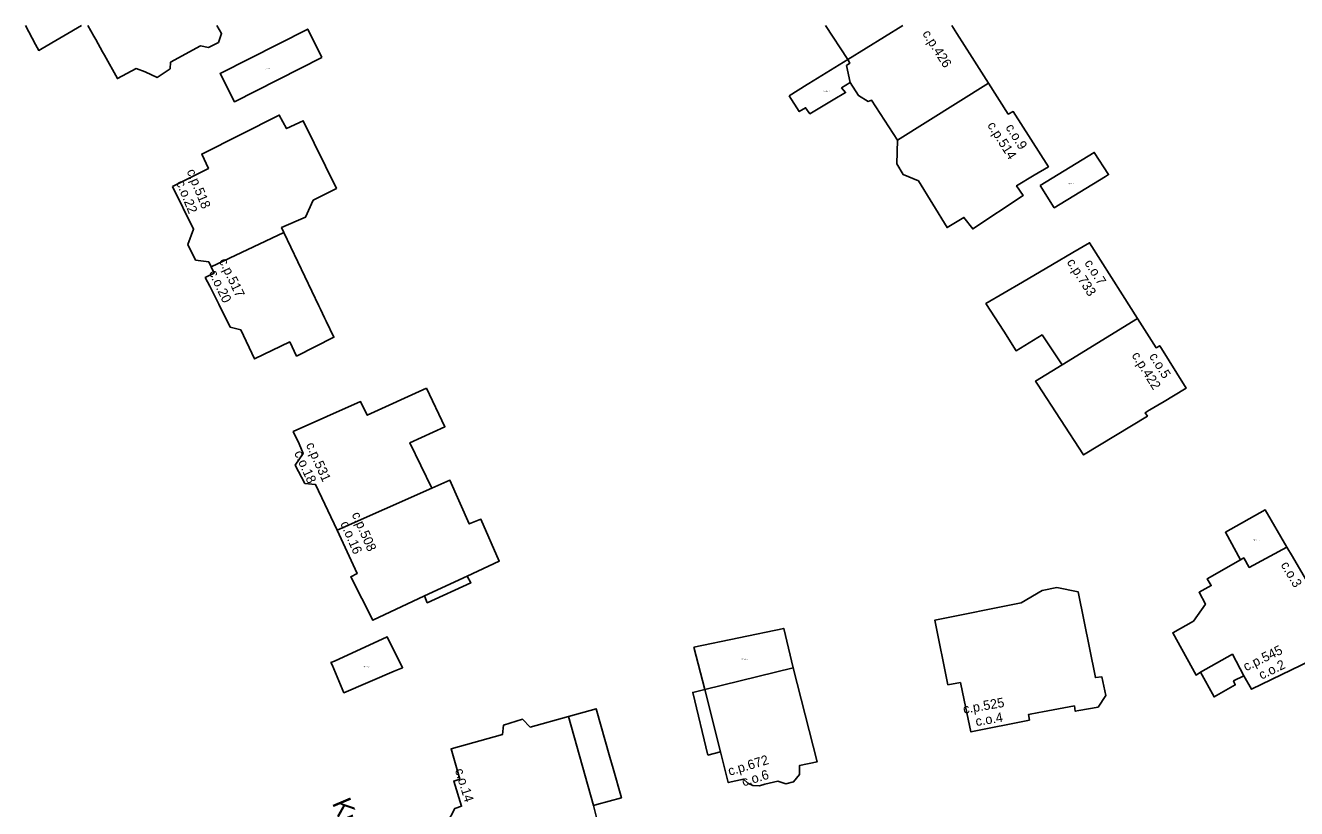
# Model space of a CAD drawing. Extents: x -600391 to -599491, y -1160176 to -1159402.
# Drawn here: x -600139.6 to -600005.8, y -1159484.2 to -1159401.8 of the extents above; entities that cross this region are included whole.
import ezdxf

# ---------------------------------------------------------------- set-up
doc = ezdxf.new("R2010")
doc.units = 0
for name, color, linetype in [('Level 10', 7, 'Continuous'), ('Level 11', 7, 'Continuous'), ('Level 12', 7, 'Continuous'), ('Level 24', 7, 'Continuous'), ('Level 25', 7, 'Continuous'), ('Level 61', 7, 'Continuous'), ('Level 62', 7, 'Continuous')]:
    doc.layers.add(name, color=color, linetype=linetype)

msp = doc.modelspace()

# ---------------------------------------------------------------- linework, layer by layer
at = {"layer": 'Level 61'}
for p, q in [((-600138.53, -1159403.77), (-600139.6, -1159401.77)), ((-600133.7, -1159401.77), (-600137.84, -1159404.2)), ((-600132.39, -1159402.91), (-600133.02, -1159401.77)), ((-600119.44, -1159401.77), (-600118.95, -1159402.63)), ((-600053.03, -1159405.36), (-600055.35, -1159401.77)), ((-600047.22, -1159401.77), (-600053.03, -1159405.36)), ((-600053.03, -1159405.36), (-600047.22, -1159401.77)), ((-600042.08, -1159401.77), (-600041.53, -1159402.63))]:
    msp.add_line(p, q, dxfattribs=at)
for points in [[(-600119.11, -1159406.82), (-600109.88, -1159402.16)], [(-600109.88, -1159402.16), (-600108.38, -1159405.14)], [(-600132.2, -1159403.26), (-600132.39, -1159402.91)], [(-600131.48, -1159404.56), (-600132.2, -1159403.26)], [(-600119.27, -1159403.55), (-600120.32, -1159404.11)], [(-600118.95, -1159402.63), (-600119.27, -1159403.55)], [(-600041.53, -1159402.63), (-600039.92, -1159405.16)], [(-600138.19, -1159404.4), (-600138.53, -1159403.77)], [(-600137.84, -1159404.2), (-600138.19, -1159404.4)], [(-600131.29, -1159404.91), (-600131.48, -1159404.56)], [(-600129.92, -1159407.37), (-600131.29, -1159404.91)], [(-600121.18, -1159403.92), (-600124.33, -1159405.65)], [(-600120.32, -1159404.11), (-600121.18, -1159403.92)], [(-600127.95, -1159406.31), (-600129.92, -1159407.37)], [(-600126.98, -1159406.66), (-600127.95, -1159406.31)], [(-600124.33, -1159405.65), (-600124.36, -1159406.33)], [(-600108.38, -1159405.14), (-600117.6, -1159409.81)], [(-600057.13, -1159407.89), (-600053.03, -1159405.36)], [(-600052.79, -1159405.74), (-600053.15, -1159406)], [(-600053.15, -1159406), (-600052.79, -1159405.74)], [(-600053.15, -1159406), (-600052.78, -1159407.77)], [(-600052.78, -1159407.77), (-600053.15, -1159406)], [(-600053.03, -1159405.36), (-600052.79, -1159405.74)], [(-600052.79, -1159405.74), (-600053.03, -1159405.36)], [(-600039.92, -1159405.16), (-600038.19, -1159407.86)], [(-600125.74, -1159407.25), (-600126.98, -1159406.66)], [(-600124.36, -1159406.33), (-600125.74, -1159407.25)], [(-600117.6, -1159409.81), (-600119.11, -1159406.82)], [(-600059.18, -1159409.18), (-600057.29, -1159407.99)], [(-600057.29, -1159407.99), (-600057.13, -1159407.89)], [(-600053.25, -1159408.83), (-600054.57, -1159409.61)], [(-600052.78, -1159407.77), (-600053.68, -1159408.35)], [(-600053.68, -1159408.35), (-600053.25, -1159408.83)], [(-600051.9, -1159409.15), (-600052.78, -1159407.77)], [(-600047.77, -1159413.85), (-600038.19, -1159407.86)], [(-600038.19, -1159407.86), (-600047.77, -1159413.85)], [(-600038.19, -1159407.86), (-600036.13, -1159411.1)], [(-600058.13, -1159410.84), (-600059.18, -1159409.18)], [(-600054.72, -1159409.7), (-600057.01, -1159411.06)], [(-600054.57, -1159409.61), (-600054.72, -1159409.7)], [(-600050.86, -1159409.76), (-600051.9, -1159409.15)], [(-600050.54, -1159409.62), (-600050.86, -1159409.76)], [(-600047.77, -1159413.85), (-600050.54, -1159409.62)], [(-600121.04, -1159415.31), (-600112.88, -1159411.21)], [(-600112.88, -1159411.21), (-600112.1, -1159412.63)], [(-600057.47, -1159410.43), (-600058.13, -1159410.84)], [(-600057.01, -1159411.06), (-600057.47, -1159410.43)], [(-600036.13, -1159411.1), (-600035.6, -1159410.83)], [(-600035.6, -1159410.83), (-600031.89, -1159416.64)], [(-600112.1, -1159412.63), (-600110.35, -1159411.81)], [(-600110.35, -1159411.81), (-600106.85, -1159418.93)], [(-600047.87, -1159416.35), (-600047.77, -1159413.85)], [(-600120.33, -1159416.82), (-600121.04, -1159415.31)], [(-600032.75, -1159418.63), (-600027.07, -1159415.13)], [(-600027.07, -1159415.13), (-600025.57, -1159417.47)], [(-600124.11, -1159418.71), (-600120.33, -1159416.82)], [(-600047.18, -1159417.47), (-600047.87, -1159416.35)], [(-600031.89, -1159416.64), (-600033.41, -1159417.53)], [(-600045.58, -1159418.12), (-600047.18, -1159417.47)], [(-600042.56, -1159423.05), (-600045.58, -1159418.12)], [(-600033.41, -1159417.53), (-600035.24, -1159418.64)], [(-600025.89, -1159417.66), (-600031.29, -1159420.96)], [(-600025.57, -1159417.47), (-600025.89, -1159417.66)], [(-600121.9, -1159423.23), (-600124.11, -1159418.71)], [(-600106.85, -1159418.93), (-600109.3, -1159420.17)], [(-600034.55, -1159419.67), (-600039.86, -1159423.19)], [(-600035.24, -1159418.64), (-600034.55, -1159419.67)], [(-600031.29, -1159420.96), (-600032.75, -1159418.63)], [(-600109.3, -1159420.17), (-600110.1, -1159421.94)], [(-600110.1, -1159421.94), (-600112.63, -1159423.05)], [(-600040.79, -1159421.98), (-600042.56, -1159423.05)], [(-600039.86, -1159423.19), (-600040.79, -1159421.98)], [(-600122.51, -1159424.82), (-600121.9, -1159423.23)], [(-600120.05, -1159427.18), (-600112.39, -1159423.56)], [(-600112.39, -1159423.56), (-600120.05, -1159427.18)], [(-600112.63, -1159423.05), (-600112.39, -1159423.56)], [(-600112.39, -1159423.56), (-600108.7, -1159431.29)], [(-600121.69, -1159426.47), (-600122.51, -1159424.82)], [(-600029.32, -1159425.67), (-600027.56, -1159424.64)], [(-600027.56, -1159424.64), (-600024.08, -1159430.14)], [(-600031.48, -1159426.94), (-600029.32, -1159425.67)], [(-600120.3, -1159426.67), (-600121.69, -1159426.47)], [(-600120.05, -1159427.18), (-600120.3, -1159426.67)], [(-600119.73, -1159427.84), (-600120.05, -1159427.18)], [(-600034.62, -1159428.78), (-600031.48, -1159426.94)], [(-600120.66, -1159428.31), (-600119.73, -1159427.84)], [(-600120.2, -1159429.22), (-600120.66, -1159428.31)], [(-600038.48, -1159431.05), (-600034.62, -1159428.78)], [(-600120.02, -1159429.58), (-600120.2, -1159429.22)], [(-600119.43, -1159430.76), (-600120.02, -1159429.58)], [(-600024.08, -1159430.14), (-600022.52, -1159432.61)], [(-600119.25, -1159431.12), (-600119.43, -1159430.76)], [(-600118.03, -1159433.55), (-600119.25, -1159431.12)], [(-600108.7, -1159431.29), (-600108.53, -1159431.65)], [(-600108.53, -1159431.65), (-600108.1, -1159432.54)], [(-600036.6, -1159433.97), (-600038.48, -1159431.05)], [(-600108.1, -1159432.54), (-600107.93, -1159432.9)], [(-600107.93, -1159432.9), (-600107.12, -1159434.6)], [(-600030.46, -1159437.5), (-600022.52, -1159432.61)], [(-600022.52, -1159432.61), (-600030.46, -1159437.5)], [(-600022.52, -1159432.61), (-600020.56, -1159435.7)], [(-600116.91, -1159433.83), (-600118.03, -1159433.55)], [(-600115.47, -1159436.88), (-600116.91, -1159433.83)], [(-600035.3, -1159436.01), (-600036.6, -1159433.97)], [(-600032.57, -1159434.35), (-600035.3, -1159436.01)], [(-600030.46, -1159437.5), (-600032.57, -1159434.35)], [(-600111.78, -1159435.08), (-600115.47, -1159436.88)], [(-600111.05, -1159436.57), (-600111.78, -1159435.08)], [(-600107.12, -1159434.6), (-600111.05, -1159436.57)], [(-600020.56, -1159435.7), (-600020.18, -1159435.49)], [(-600020.18, -1159435.49), (-600017.41, -1159439.96)], [(-600033.24, -1159439.21), (-600030.46, -1159437.5)], [(-600033.04, -1159439.52), (-600033.24, -1159439.21)], [(-600028.2, -1159446.99), (-600033.04, -1159439.52)], [(-600103.61, -1159442.8), (-600097.36, -1159439.94)], [(-600097.36, -1159439.94), (-600095.44, -1159444.01)], [(-600017.41, -1159439.96), (-600019.9, -1159441.45)], [(-600111.4, -1159444.52), (-600104.32, -1159441.36)], [(-600104.32, -1159441.36), (-600103.61, -1159442.8)], [(-600021.28, -1159442.28), (-600021.71, -1159442.54)], [(-600020.98, -1159442.1), (-600021.28, -1159442.28)], [(-600020.2, -1159441.63), (-600020.98, -1159442.1)], [(-600019.9, -1159441.45), (-600020.2, -1159441.63)], [(-600021.47, -1159442.89), (-600028.2, -1159446.99)], [(-600021.71, -1159442.54), (-600021.47, -1159442.89)], [(-600110.78, -1159445.82), (-600111.4, -1159444.52)], [(-600095.44, -1159444.01), (-600099.12, -1159445.7)], [(-600110.36, -1159446.82), (-600110.78, -1159445.82)], [(-600099.12, -1159445.7), (-600096.8, -1159450.48)], [(-600111.2, -1159448.06), (-600110.36, -1159446.82)], [(-600110.17, -1159449.98), (-600111.2, -1159448.06)], [(-600109.05, -1159450.1), (-600110.17, -1159449.98)], [(-600106.79, -1159454.92), (-600109.05, -1159450.1)], [(-600096.8, -1159450.48), (-600106.79, -1159454.92)], [(-600106.79, -1159454.92), (-600096.8, -1159450.48)], [(-600096.8, -1159450.48), (-600094.91, -1159449.64)], [(-600094.91, -1159449.64), (-600092.88, -1159454.25)], [(-600013.27, -1159455.13), (-600009.07, -1159452.78)], [(-600009.07, -1159452.78), (-600006.79, -1159456.69)], [(-600092.88, -1159454.25), (-600091.64, -1159453.76)], [(-600091.64, -1159453.76), (-600089.72, -1159458.16)], [(-600104.67, -1159459.46), (-600106.79, -1159454.92)], [(-600011.66, -1159458.03), (-600013.27, -1159455.13)], [(-600006.79, -1159456.69), (-600010.75, -1159458.82)], [(-600010.75, -1159458.82), (-600006.79, -1159456.69)], [(-600006.79, -1159456.69), (-600006.21, -1159457.68)], [(-600089.72, -1159458.16), (-600093.1, -1159459.76)], [(-600015.18, -1159460.01), (-600011.66, -1159458.03)], [(-600011.34, -1159457.83), (-600011.66, -1159458.03)], [(-600011.66, -1159458.03), (-600011.34, -1159457.83)], [(-600010.75, -1159458.82), (-600011.34, -1159457.83)], [(-600011.34, -1159457.83), (-600010.75, -1159458.82)], [(-600006.21, -1159457.68), (-600003.6, -1159462.13)], [(-600105.35, -1159459.81), (-600104.67, -1159459.46)], [(-600103.04, -1159464.39), (-600105.35, -1159459.81)], [(-600097.59, -1159461.82), (-600093.1, -1159459.76)], [(-600093.1, -1159459.76), (-600097.59, -1159461.82)], [(-600093.1, -1159459.76), (-600092.69, -1159460.44)], [(-600092.69, -1159460.44), (-600097.29, -1159462.54)], [(-600032.56, -1159461.26), (-600031, -1159460.95)], [(-600031, -1159460.95), (-600028.75, -1159461.41)], [(-600016.04, -1159461.43), (-600014.76, -1159460.73)], [(-600014.76, -1159460.73), (-600015.18, -1159460.01)], [(-600097.59, -1159461.82), (-600103.04, -1159464.39)], [(-600097.29, -1159462.54), (-600097.59, -1159461.82)], [(-600034.75, -1159462.54), (-600032.56, -1159461.26)], [(-600028.75, -1159461.41), (-600026.94, -1159470.42)], [(-600015.37, -1159462.68), (-600016.04, -1159461.43)], [(-600043.84, -1159464.37), (-600034.75, -1159462.54)], [(-600016.63, -1159464.47), (-600015.37, -1159462.68)], [(-600042.49, -1159471.2), (-600043.84, -1159464.37)], [(-600018.81, -1159465.7), (-600016.63, -1159464.47)], [(-600107.07, -1159468.68), (-600101.53, -1159466.13)], [(-600101.53, -1159466.13), (-600099.89, -1159469.39)], [(-600069.22, -1159467.21), (-600059.77, -1159465.25)], [(-600059.77, -1159465.25), (-600058.76, -1159469.38)], [(-600016.35, -1159470.15), (-600018.81, -1159465.7)], [(-600068.08, -1159471.68), (-600069.22, -1159467.21)], [(-600107.43, -1159468.85), (-600107.07, -1159468.68)], [(-600107.32, -1159469.09), (-600107.43, -1159468.85)], [(-600106.24, -1159471.61), (-600107.32, -1159469.09)], [(-600012.53, -1159467.97), (-600015.87, -1159469.86)], [(-600015.87, -1159469.86), (-600012.53, -1159467.97)], [(-600011.32, -1159470.22), (-600012.53, -1159467.97)], [(-600012.53, -1159467.97), (-600011.32, -1159470.22)], [(-600003.19, -1159468.1), (-600010.53, -1159471.65)], [(-600100.77, -1159469.73), (-600106.07, -1159472.01)], [(-600099.89, -1159469.39), (-600100.77, -1159469.73)], [(-600068.08, -1159471.68), (-600058.76, -1159469.38)], [(-600058.76, -1159469.38), (-600068.08, -1159471.68)], [(-600058.76, -1159469.38), (-600056.26, -1159479.3)], [(-600026.94, -1159470.42), (-600026.28, -1159470.34)], [(-600026.28, -1159470.34), (-600025.85, -1159472.31)], [(-600015.87, -1159469.86), (-600016.35, -1159470.15)], [(-600014.45, -1159472.45), (-600015.87, -1159469.86)], [(-600011.32, -1159470.22), (-600012.41, -1159470.77)], [(-600010.53, -1159471.65), (-600011.32, -1159470.22)], [(-600106.07, -1159472.01), (-600106.24, -1159471.61)], [(-600069.35, -1159471.99), (-600068.08, -1159471.68)], [(-600066.42, -1159478.24), (-600068.08, -1159471.68)], [(-600068.08, -1159471.68), (-600066.42, -1159478.24)], [(-600041.17, -1159470.94), (-600042.49, -1159471.2)], [(-600040.77, -1159472.81), (-600041.17, -1159470.94)], [(-600012.22, -1159471.19), (-600014.45, -1159472.45)], [(-600012.41, -1159470.77), (-600012.22, -1159471.19)], [(-600067.75, -1159478.58), (-600069.35, -1159471.99)], [(-600040.05, -1159476.14), (-600040.77, -1159472.81)], [(-600025.85, -1159472.31), (-600026.66, -1159473.55)], [(-600086.47, -1159475.63), (-600082.44, -1159474.51)], [(-600082.44, -1159474.51), (-600079.5, -1159473.7)], [(-600079.78, -1159483.87), (-600082.44, -1159474.51)], [(-600082.44, -1159474.51), (-600079.78, -1159483.87)], [(-600079.5, -1159473.7), (-600078.06, -1159478.8)], [(-600032.92, -1159474.11), (-600034, -1159474.31)], [(-600034, -1159474.31), (-600033.89, -1159474.9)], [(-600032.52, -1159474.03), (-600032.92, -1159474.11)], [(-600029.16, -1159473.4), (-600032.52, -1159474.03)], [(-600029.08, -1159473.96), (-600029.16, -1159473.4)], [(-600028.69, -1159473.89), (-600029.08, -1159473.96)], [(-600026.66, -1159473.55), (-600028.69, -1159473.89)], [(-600089.38, -1159476.43), (-600089.26, -1159475.42)], [(-600089.26, -1159475.42), (-600087.28, -1159474.8)], [(-600087.28, -1159474.8), (-600086.47, -1159475.63)], [(-600033.89, -1159474.9), (-600040.05, -1159476.14)], [(-600094.78, -1159477.93), (-600089.38, -1159476.43)], [(-600093.88, -1159481.13), (-600094.78, -1159477.93)], [(-600066.42, -1159478.24), (-600067.75, -1159478.58)], [(-600065.6, -1159481.47), (-600066.42, -1159478.24)], [(-600078.06, -1159478.8), (-600077.72, -1159479.99)], [(-600056.26, -1159479.3), (-600058.12, -1159479.69)], [(-600058.12, -1159479.69), (-600058.12, -1159480.63)], [(-600094.5, -1159481.32), (-600093.88, -1159481.13)], [(-600077.72, -1159479.99), (-600076.85, -1159483.08)], [(-600063.99, -1159481.11), (-600065.6, -1159481.47)], [(-600063.54, -1159481.54), (-600063.99, -1159481.11)], [(-600058.12, -1159480.63), (-600058.72, -1159481.38)], [(-600093.68, -1159483.96), (-600094.5, -1159481.32)], [(-600063.01, -1159481.78), (-600063.54, -1159481.54)], [(-600062.33, -1159481.82), (-600063.01, -1159481.78)], [(-600061.75, -1159481.64), (-600062.33, -1159481.82)], [(-600060.37, -1159481.31), (-600061.75, -1159481.64)], [(-600059.55, -1159481.6), (-600060.37, -1159481.31)], [(-600058.72, -1159481.38), (-600059.55, -1159481.6)], [(-600079.44, -1159483.78), (-600079.78, -1159483.87)], [(-600079.78, -1159483.87), (-600079.43, -1159485.28)], [(-600076.85, -1159483.08), (-600079.44, -1159483.78)], [(-600095.19, -1159485.73), (-600094.4, -1159484.21)], [(-600094.4, -1159484.21), (-600093.68, -1159483.96)]]:
    msp.add_lwpolyline(points, dxfattribs=at)
at = {"layer": 'Level 62'}
for points in [[(-600133.7, -1159401.77), (-600137.84, -1159404.2), (-600138.19, -1159404.4), (-600138.53, -1159403.77), (-600139.6, -1159401.77)], [(-600131.48, -1159404.56), (-600132.2, -1159403.26), (-600132.39, -1159402.91), (-600133.02, -1159401.77)], [(-600119.44, -1159401.77), (-600118.95, -1159402.63), (-600119.27, -1159403.55), (-600120.32, -1159404.11), (-600121.18, -1159403.92), (-600124.33, -1159405.65), (-600124.36, -1159406.33), (-600125.74, -1159407.25), (-600126.98, -1159406.66), (-600127.95, -1159406.31), (-600129.92, -1159407.37), (-600131.29, -1159404.91), (-600131.48, -1159404.56)], [(-600108.38, -1159405.14), (-600117.6, -1159409.81), (-600119.11, -1159406.82), (-600109.88, -1159402.16), (-600108.38, -1159405.14)], [(-600047.22, -1159401.77), (-600053.03, -1159405.36), (-600055.35, -1159401.77)], [(-600038.19, -1159407.86), (-600047.77, -1159413.85), (-600050.54, -1159409.62), (-600050.86, -1159409.76), (-600051.9, -1159409.15), (-600052.78, -1159407.77), (-600053.15, -1159406), (-600052.79, -1159405.74), (-600053.03, -1159405.36), (-600047.22, -1159401.77)], [(-600042.08, -1159401.77), (-600041.53, -1159402.63), (-600039.92, -1159405.16), (-600038.19, -1159407.86)], [(-600059.18, -1159409.18), (-600057.29, -1159407.99), (-600057.13, -1159407.89), (-600053.03, -1159405.36), (-600052.79, -1159405.74), (-600053.15, -1159406), (-600052.78, -1159407.77), (-600053.68, -1159408.35), (-600053.25, -1159408.83), (-600054.57, -1159409.61), (-600054.72, -1159409.7), (-600057.01, -1159411.06), (-600057.47, -1159410.43), (-600058.13, -1159410.84), (-600059.18, -1159409.18)], [(-600038.19, -1159407.86), (-600036.13, -1159411.1), (-600035.6, -1159410.83), (-600031.89, -1159416.64), (-600033.41, -1159417.53), (-600035.24, -1159418.64), (-600034.55, -1159419.67), (-600039.86, -1159423.19), (-600040.79, -1159421.98), (-600042.56, -1159423.05), (-600045.58, -1159418.12), (-600047.18, -1159417.47), (-600047.87, -1159416.35), (-600047.77, -1159413.85), (-600038.19, -1159407.86)], [(-600124.11, -1159418.71), (-600120.33, -1159416.82), (-600121.04, -1159415.31), (-600112.88, -1159411.21), (-600112.1, -1159412.63), (-600110.35, -1159411.81), (-600106.85, -1159418.93), (-600109.3, -1159420.17), (-600110.1, -1159421.94), (-600112.63, -1159423.05), (-600112.39, -1159423.56), (-600120.05, -1159427.18), (-600120.3, -1159426.67), (-600121.69, -1159426.47), (-600122.51, -1159424.82), (-600121.9, -1159423.23), (-600124.11, -1159418.71)], [(-600032.75, -1159418.63), (-600027.07, -1159415.13), (-600025.57, -1159417.47), (-600025.89, -1159417.66), (-600031.29, -1159420.96), (-600032.75, -1159418.63)], [(-600108.7, -1159431.29), (-600108.53, -1159431.65), (-600108.1, -1159432.54), (-600107.93, -1159432.9), (-600107.12, -1159434.6), (-600111.05, -1159436.57), (-600111.78, -1159435.08), (-600115.47, -1159436.88), (-600116.91, -1159433.83), (-600118.03, -1159433.55), (-600119.25, -1159431.12), (-600119.43, -1159430.76), (-600120.02, -1159429.58), (-600120.2, -1159429.22), (-600120.66, -1159428.31), (-600119.73, -1159427.84), (-600120.05, -1159427.18), (-600112.39, -1159423.56), (-600108.7, -1159431.29)], [(-600029.32, -1159425.67), (-600027.56, -1159424.64), (-600024.08, -1159430.14), (-600022.52, -1159432.61), (-600030.46, -1159437.5), (-600032.57, -1159434.35), (-600035.3, -1159436.01), (-600036.6, -1159433.97), (-600038.48, -1159431.05), (-600034.62, -1159428.78), (-600031.48, -1159426.94), (-600029.32, -1159425.67)], [(-600033.04, -1159439.52), (-600033.24, -1159439.21), (-600030.46, -1159437.5), (-600022.52, -1159432.61), (-600020.56, -1159435.7), (-600020.18, -1159435.49), (-600017.41, -1159439.96), (-600019.9, -1159441.45), (-600020.2, -1159441.63), (-600020.98, -1159442.1), (-600021.28, -1159442.28), (-600021.71, -1159442.54), (-600021.47, -1159442.89), (-600028.2, -1159446.99), (-600033.04, -1159439.52)], [(-600097.36, -1159439.94), (-600095.44, -1159444.01), (-600099.12, -1159445.7), (-600096.8, -1159450.48), (-600106.79, -1159454.92), (-600109.05, -1159450.1), (-600110.17, -1159449.98), (-600111.2, -1159448.06), (-600110.36, -1159446.82), (-600110.78, -1159445.82), (-600111.4, -1159444.52), (-600104.32, -1159441.36), (-600103.61, -1159442.8), (-600097.36, -1159439.94)], [(-600096.8, -1159450.48), (-600094.91, -1159449.64), (-600092.88, -1159454.25), (-600091.64, -1159453.76), (-600089.72, -1159458.16), (-600093.1, -1159459.76), (-600097.59, -1159461.82), (-600103.04, -1159464.39), (-600105.35, -1159459.81), (-600104.67, -1159459.46), (-600106.79, -1159454.92), (-600096.8, -1159450.48)], [(-600006.79, -1159456.69), (-600010.75, -1159458.82), (-600011.34, -1159457.83), (-600011.66, -1159458.03), (-600013.27, -1159455.13), (-600009.07, -1159452.78), (-600006.79, -1159456.69)], [(-600015.87, -1159469.86), (-600016.35, -1159470.15), (-600018.81, -1159465.7), (-600016.63, -1159464.47), (-600015.37, -1159462.68), (-600016.04, -1159461.43), (-600014.76, -1159460.73), (-600015.18, -1159460.01), (-600011.66, -1159458.03), (-600011.34, -1159457.83), (-600010.75, -1159458.82), (-600006.79, -1159456.69), (-600006.21, -1159457.68), (-600003.6, -1159462.13), (-600003.46, -1159462.37), (-600003.82, -1159462.61), (-600002.22, -1159465.43), (-600000.63, -1159465.94), (-600001.39, -1159468.49), (-600003.19, -1159468.1), (-600010.53, -1159471.65), (-600011.32, -1159470.22), (-600012.53, -1159467.97), (-600015.87, -1159469.86)], [(-600097.59, -1159461.82), (-600093.1, -1159459.76), (-600092.69, -1159460.44), (-600097.29, -1159462.54), (-600097.59, -1159461.82)], [(-600042.49, -1159471.2), (-600043.84, -1159464.37), (-600034.75, -1159462.54), (-600032.56, -1159461.26), (-600031, -1159460.95), (-600028.75, -1159461.41), (-600026.94, -1159470.42), (-600026.28, -1159470.34), (-600025.85, -1159472.31), (-600026.66, -1159473.55), (-600028.69, -1159473.89), (-600029.08, -1159473.96), (-600029.16, -1159473.4), (-600032.52, -1159474.03), (-600032.92, -1159474.11), (-600034, -1159474.31), (-600033.89, -1159474.9), (-600040.05, -1159476.14), (-600040.77, -1159472.81), (-600041.17, -1159470.94), (-600042.49, -1159471.2)], [(-600100.77, -1159469.73), (-600106.07, -1159472.01), (-600106.24, -1159471.61), (-600107.32, -1159469.09), (-600107.43, -1159468.85), (-600107.07, -1159468.68), (-600101.53, -1159466.13), (-600099.89, -1159469.39), (-600100.77, -1159469.73)], [(-600069.22, -1159467.21), (-600059.77, -1159465.25), (-600058.76, -1159469.38), (-600068.08, -1159471.68), (-600069.22, -1159467.21)], [(-600015.87, -1159469.86), (-600012.53, -1159467.97), (-600011.32, -1159470.22), (-600012.41, -1159470.77), (-600012.22, -1159471.19), (-600014.45, -1159472.45), (-600015.87, -1159469.86)], [(-600058.76, -1159469.38), (-600056.26, -1159479.3), (-600058.12, -1159479.69), (-600058.12, -1159480.63), (-600058.72, -1159481.38), (-600059.55, -1159481.6), (-600060.37, -1159481.31), (-600061.75, -1159481.64), (-600062.33, -1159481.82), (-600063.01, -1159481.78), (-600063.54, -1159481.54), (-600063.99, -1159481.11), (-600065.6, -1159481.47), (-600066.42, -1159478.24), (-600068.08, -1159471.68), (-600058.76, -1159469.38)], [(-600067.75, -1159478.58), (-600069.35, -1159471.99), (-600068.08, -1159471.68), (-600066.42, -1159478.24), (-600067.75, -1159478.58)], [(-600082.44, -1159474.51), (-600079.78, -1159483.87), (-600079.43, -1159485.28), (-600092.21, -1159488.88), (-600092.67, -1159487.62), (-600093.47, -1159487.91), (-600094.8, -1159487.24), (-600095.19, -1159485.73), (-600094.4, -1159484.21), (-600093.68, -1159483.96), (-600094.5, -1159481.32), (-600093.88, -1159481.13), (-600094.78, -1159477.93), (-600089.38, -1159476.43), (-600089.26, -1159475.42), (-600087.28, -1159474.8), (-600086.47, -1159475.63), (-600082.44, -1159474.51)], [(-600077.72, -1159479.99), (-600076.85, -1159483.08), (-600079.44, -1159483.78), (-600079.78, -1159483.87), (-600082.44, -1159474.51), (-600079.5, -1159473.7), (-600078.06, -1159478.8), (-600077.72, -1159479.99)]]:
    msp.add_lwpolyline(points, dxfattribs=at)

# ---------------------------------------------------------------- texts
at = {"layer": 'Level 10'}
for s, rotation, p in [('c.o.9', 302.2677, (-600036.45, -1159412.5)), ('c.o.22', 292.2483, (-600123.75, -1159418.31)), ('c.o.20', 295.353, (-600120.32, -1159427.79)), ('c.o.7', 302.549, (-600028.15, -1159426.78)), ('c.o.5', 302.0515, (-600021.33, -1159436.59)), ('c.o.18', 294.1917, (-600111.33, -1159446.77)), ('c.o.16', 293.6146, (-600106.47, -1159454.2)), ('c.o.3', 300.5117, (-600007.47, -1159458.55)), ('c.o.2', 25.8117, (-600009.46, -1159470.65)), ('c.o.4', 9.7703, (-600039.49, -1159475.54)), ('c.o.14', 287.259, (-600094.4, -1159480.15)), ('c.o.6', 16.893, (-600064.01, -1159481.89))]:
    msp.add_text(s, height=1, rotation=rotation, dxfattribs=at).set_placement(p)
at = {"layer": 'Level 11'}
msp.add_text('Krondlova', height=2, rotation=292.9722, dxfattribs=at).set_placement((-600107.34, -1159483.62))
at = {"layer": 'Level 12'}
for s, rotation, p in [('c.p.426', 302.4171, (-600045.21, -1159402.63)), ('c.p.514', 302.2677, (-600038.37, -1159412.28)), ('c.p.518', 292.2483, (-600122.64, -1159417.11)), ('c.p.517', 295.353, (-600119.25, -1159426.55)), ('c.p.733', 302.549, (-600030, -1159426.69)), ('c.p.422', 302.0515, (-600023.17, -1159436.5)), ('c.p.531', 294.1917, (-600110.09, -1159445.91)), ('c.p.508', 293.6146, (-600105.27, -1159453.23)), ('c.p.545', 25.8117, (-600011.09, -1159469.77)), ('c.p.525', 9.7703, (-600040.8, -1159474.24)), ('c.p.672', 16.893, (-600065.46, -1159480.77))]:
    msp.add_text(s, height=1, rotation=rotation, dxfattribs=at).set_placement(p)
at = {"layer": 'Level 24'}
msp.add_text('c.z.2173', height=0.1, dxfattribs=at).set_placement((-600114.37, -1159406.4))
at = {"layer": 'Level 25'}
for s, p in [('c.pp.426_A', (-600055.61, -1159408.73)), ('c.pp.514_A', (-600029.88, -1159418.46)), ('c.pp.545_A', (-600010.36, -1159455.99)), ('c.pp.508_A', (-600104.07, -1159469.3)), ('c.pp.672_A', (-600064.27, -1159468.52))]:
    msp.add_text(s, height=0.1, dxfattribs=at).set_placement(p)

doc.saveas('drawing.dxf')
